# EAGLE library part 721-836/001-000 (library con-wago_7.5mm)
Serie 721, Stiftleiste mit abgewinkelten Einlötstiften / Series 721, Male connector with angled solder pins Polzahl / Pole No.: 6 Rastermaß / Pitch: 7.5 mm Bemessungsspannung / Rated Voltage: 630 V Nennstrom / Nominal Current: 12 A Lötstiftlänge: / Solder Pin Length: 3.8 mm Farbe / Color: lichtgrau / light gray Stand: 01.01.2012. Die jeweils aktuellen Daten zu diesem Artikel finden Sie in unserem Produktkatalog, den Sie unter www.wago.com einsehen können. As of: 01/01/2012. Please find the newest data for this article in our product catalogue, which can be viewed under www.wago.com.
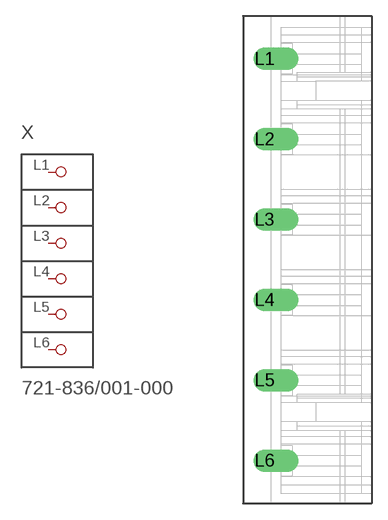
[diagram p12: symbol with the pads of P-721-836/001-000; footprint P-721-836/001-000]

Designator prefix X

## 721-836/001-000  [P-721-836/001-000]
L1  P1
L2  P2
L3  P3
L4  P4
L5  P5
L6  P6

## Footprint P-721-836/001-000 (pad centres in mm)
drill 1.4 offset: L1 -4,18.75; L2 -4,11.25; L3 -4,3.75; L4 -4,-3.75; L5 -4,-11.25; L6 -4,-18.75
